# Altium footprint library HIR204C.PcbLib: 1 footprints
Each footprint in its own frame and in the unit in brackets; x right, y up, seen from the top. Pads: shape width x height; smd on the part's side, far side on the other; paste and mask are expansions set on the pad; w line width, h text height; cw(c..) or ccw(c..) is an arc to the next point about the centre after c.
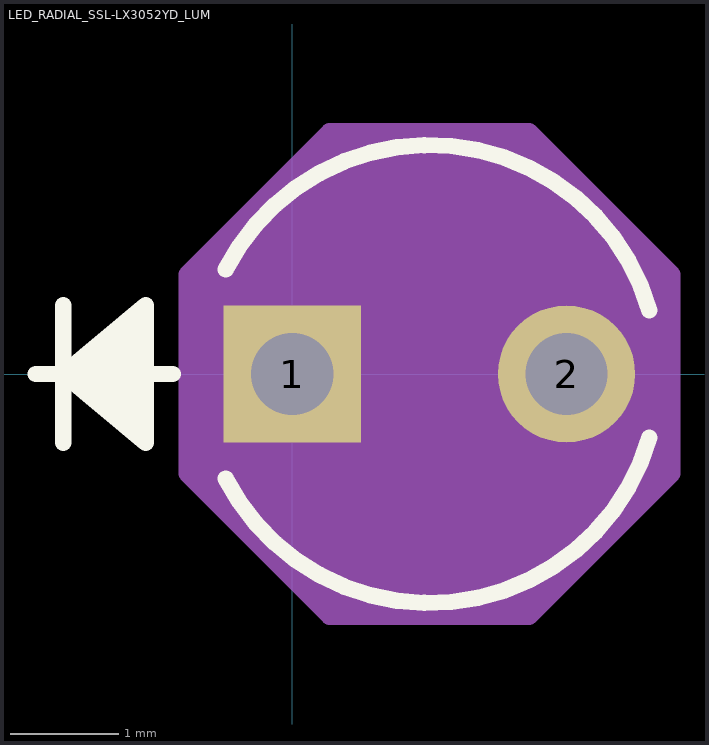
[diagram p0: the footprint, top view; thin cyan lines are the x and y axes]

## LED_RADIAL_SSL-LX3052YD_LUM [mil]
pads (2):
  rect 50x50 / inner round 60 / far side rect 50x50 hole 30 paste-25 mask+0: 1(0,0)
  round 50 / inner round 60 / far side round 50 hole 30 paste-25 mask+0: 2(100,0)
Top Overlay:
  lines w6: -93.5,0 -43.5,0 ; -83.5,-25 -83.5,25 ; -53.5,-20 -83.5,0 ; -53.5,-15 -83.5,0 ; -53.5,-10 -83.5,0 ; -53.5,-5 -83.5,0 ; -53.5,5 -83.5,0 ; -53.5,10 -83.5,0 ; -53.5,15 -83.5,0 ; -53.5,20 -83.5,0 ; -24.3,-38.1 ccw(c50,0) 130.21,-23.22 ; -24.3,38.1 cw(c50,0) 130.21,23.22 ; -83.5,0 -53.5,25 -53.5,-25 -83.5,0
Mechanical 13:
  circle w0: c50,0 r78.5
  lines w1: -93.5,0 -43.5,0 ; -83.5,-25 -83.5,25 ; -53.5,-20 -83.5,0 ; -53.5,-15 -83.5,0 ; -53.5,-10 -83.5,0 ; -53.5,-5 -83.5,0 ; -53.5,5 -83.5,0 ; -53.5,10 -83.5,0 ; -53.5,15 -83.5,0 ; -53.5,20 -83.5,0 ; -83.5,0 -53.5,25 -53.5,-25 -83.5,0
Mechanical 15:
  region: -38.5,36.44 13.56,88.5 86.44,88.5 138.5,36.44 138.5,-36.44 86.44,-88.5 13.56,-88.5 -38.5,-36.44
  lines w6: -38.5,-36.44 13.56,-88.5 86.44,-88.5 138.5,-36.44 138.5,36.44 86.44,88.5 13.56,88.5 -38.5,36.44 -38.5,-36.44
3D body: height 206.61, standoff -160, extent -28.94,-78.38 128.04,78.38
